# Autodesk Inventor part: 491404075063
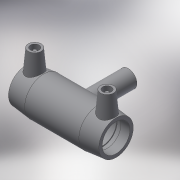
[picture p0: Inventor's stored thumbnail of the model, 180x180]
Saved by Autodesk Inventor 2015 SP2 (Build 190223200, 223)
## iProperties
Created: 2017-06
Part Number: 491404075063
Material: Generic
Description: PLASSON REDUCING TEE 75x63x75
Document SubType Name: Modeling
Designer: KIM
Mass: 57.3761 g
Surface Area: 241.06 cm^2
Volume: 57.3761 cm^3
Density: 1 g/cm^3
Appearance: Default
Author: KIM
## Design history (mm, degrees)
derived "491404.ipt"
feature "Solid1::491404.ipt"
tag "TaggingFeature1"
body "Solid1"
other parameters: "d0" = 196, "d1" = 75, "d2" = 96, "d3" = 63, "d4" = 39.2, "d5" = 86.4, "d6" = 71.25, "d7" = 75, "d8" = 168 deg, "d10" = 25.2, "d11" = 8.4, "d13" = 196, "d14" = 17.6296, "d17" = 67.5, "d18" = 75, "d19" = 3.52592, "d20" = 168 deg, "d22" = 89.28, "d23" = 96, "d25" = 135 deg, "d26" = 137.2, "d29" = 62, "d30" = 15, "d31" = 78.4, "d34" = 5 deg, "d35" = 15, "d39" = 5 deg, "d41" = 4, "d42" = 14, "d43" = 0, "d45" = 4, "d46" = 6, "d47" = 0, "d48" = -122, "d49" = 63, "d51" = 0, "d52" = 50.4, "d54" = 0, "d55" = 86.4, "d56" = 96, "d57" = 68.6, "d58" = 135 deg, "d59" = 63, "d60" = 63, "d61" = 135 deg, "d62" = 122, "d72" = 89.18, "d73" = 44.59, "d74" = -122, "d75" = 66.15, "d77" = 0, "d78" = 50.4, "d80" = 0, "d81" = 63, "d82" = 74, "d83" = 0, "d84" = 3, "d85" = 0, "d86" = 21, "d87" = 87.4944, "d88" = 8.4, "d89" = 3, "d90" = 0, "d_" = 75, "L_" = 196, "L_1" = 63, "D_" = 96, "A_" = 62, "d_2" = 12, "H_" = 122, "d_1" = 63
